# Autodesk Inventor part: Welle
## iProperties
Shininess: 64.0
Length Units: 11269
Angle Units: 11279
Time Units: 11290
Mass Units: 11283
Length Display Precision: 3
Angle Display Precision: 2
Compacted: True
Part Number: Welle
Document SubType Name: Modeling
Created: 2004-05
Material: Standard
Designer: KWU_CAD
Manufacturer: Standard
Standards Organization: Custom
Density: 0.0
Volumn: 0.0
Area: 0.0
PropertySet Name: Model Information
Control State: 0
Master: False
Checked Out: False
Author: KWU_CAD
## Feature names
1. Drehung1 [Revolution]
